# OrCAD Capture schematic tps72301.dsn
size A
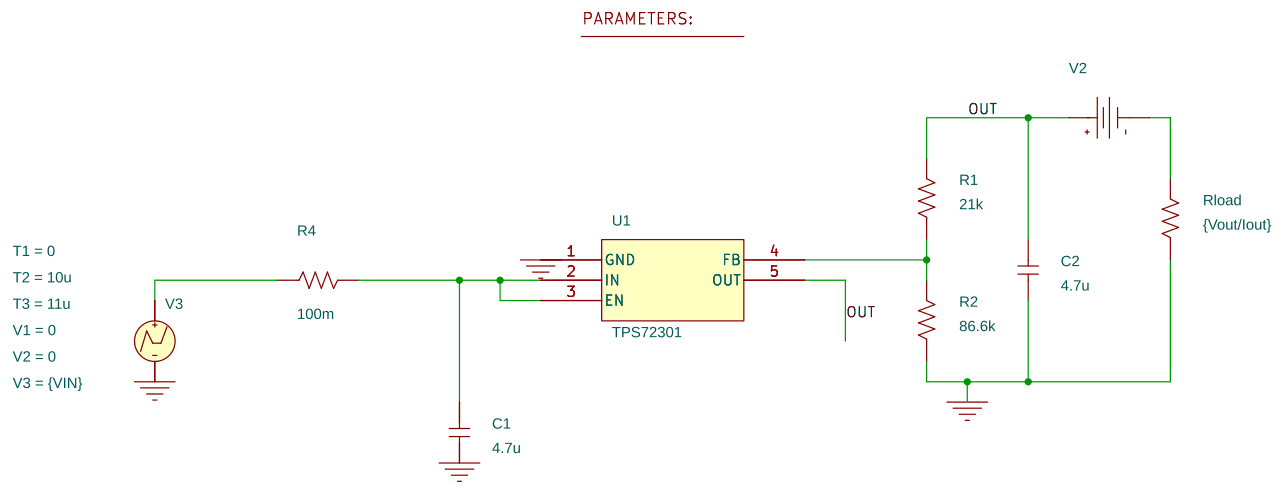
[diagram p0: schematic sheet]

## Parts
4  PARAM
C1  4.7u  [cap196]
C2  4.7u  [cap196]
R1  21k  [AXRC05]
R2  86.6k  [AXRC05]
R4  100m  [AXRC05]
Rload  {Vout/Iout}  [AXRC05]
U1  TPS72301
V2  VDC
V3  VPWL

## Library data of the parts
4 = PARAM: IOUT: 0.005; STEADY_STATE: 0; VIN: -3.25; vout: -1.5
C1 C2 = C
R1 R2 R4 Rload = R
U1 = TPS72301
V2 = VDC
V3 = VPWL: PSpiceTemplate: V^@REFDES %+ %- ?DC|DC @DC| ?AC|AC @AC|\n+PWL @T1 @V1 @T2 @V2 #T3/@T3 @V3/ #T4/@T4 @V4/ #T5/@T5 @V5/ #T6/@T6 @V6/ #T7/@T7 @V7/ #T8/@T8 @V8/ #T9/@T9 @V9/ #T10/@T10 @V10/; T1: 0; T2: 10u; T3: 11u; V1: 0; V2: 0; V3: {VIN}

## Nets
0: C1.1 C2.1 R2.1 Rload.1 U1.1(GND) V3.2(-)
OUT: C2.2 R1.2 U1.5(OUT) V2.0(+)
N00118: C1.2 R4.2 U1.2(IN) U1.3(EN)
N00235: R1.1 R2.2 U1.4(FB)
N00397: R4.1 V3.1(+)
N264433: Rload.2 V2.1(-)
